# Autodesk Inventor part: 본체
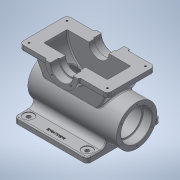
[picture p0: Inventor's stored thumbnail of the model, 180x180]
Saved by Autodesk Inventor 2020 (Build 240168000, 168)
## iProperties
Created: 2023-06
Part Number: 본체
Material: 알루미늄 6061
Document SubType Name: Modeling
Designer: mdu-01
Mass: 5748.4 g
Surface Area: 2841.69 cm^2
Volume: 2121.18 cm^3
Density: 2.71 g/cm^3
Appearance: 알루미늄 - 평지
Author: mdu-01
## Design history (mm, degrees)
sketch "스케치1"
  geometry: L1 (0, 70)-(0, -70); L2 (0, 0)-(-100, 0); L3 (0, 70)-(-45, 70); L4 (-45, 70)-(-45, 45); L5 (-45, 45)-(-100, 45); L6 (0, -70)-(-45, -70); L7 (-45, -70)-(-45, -45); L8 (-45, -45)-(-100, -45); L9 (-100, 45)-(-100, -45); 1 further point
  constraints: 18 end point, 3 perpendicular, 3 symmetric about line, 2 midpoint, 2 parallel, 1 coincident, 1 vertical
  dimensions: "d0" = 140 distance of L1.start L1.end; "d1" = 100 distance of L2.start L2.end; "d3" = 90 diameter of L4 L1; "d4" = 90 distance between parallel lines of L8 L5
revolve "회전1" sketch "스케치1" stored, may be unused: angle "d5" = 180 deg
sketch "스케치2"
  geometry: L1 (-155, -20)-(65, -20); L2 (75, -10)-(75, 100); L3 (65, 110)-(-155, 110); L4 (-165, 100)-(-165, -10); L5 (-165, -20)-(75, 110); L6 (75, -20)-(-165, 110); A1 r 10 centre (-155, 100) between (-155, 110) and (-165, 100); A2 r 10 centre (65, 100) between (75, 100) and (65, 110); A3 r 10 centre (65, -10) between (65, -20) and (75, -10); A4 r 10 centre (-155, -10) between (-165, -10) and (-155, -20); 1 further point
  constraints: 12 end point, 8 point on circle, 8 point on line, 8 tangent, 4 centre point, 3 equal radius, 2 midpoint, 2 parallel, 1 horizontal, 1 perpendicular
  dimensions: "d6" = 240 distance of L6.end L5.end; "d7" = 130 distance of L5.end L6.start; "d8" = 10 radius of A1
extrude "돌출1" join sketch "스케치2" distance "d9" = 15; taper "d10" = 0 deg
sketch "스케치3"
  geometry: C1 r 55 at (-100, 0); 1 further point
  constraints: 1 centre point
  dimensions: "d11" = 110 diameter of C1; "d12" = 100 distance of C1.centre point (0, 0)
extrude "돌출2" join sketch "스케치3" distance "d13" = 135; taper "d15" = 0 deg; dims "d14" = 107, "d16" = 0
sketch "스케치4"
  geometry: L1 (-100, -160)-(100, -160); L2 (100, -160)-(100, -145); L3 (100, -145)-(-100, -145); L4 (-100, -145)-(-100, -160); 1 further point
  constraints: 8 end point, 2 parallel, 1 horizontal, 1 perpendicular
  dimensions: "d17" = 200 distance of L3.end L2.end; "d18" = 15 distance of L2.end L1.end; "d19" = 100 distance from line of L4 point (0, 0); "d20" = 160 distance from line of L1 point (0, 0)
extrude "돌출3" join sketch "스케치4" stored distance "d21" = 200; taper "d22" = 0 deg
fillet "모깎기1" dims "d23" = 15
fillet "모깎기2" dims "d24" = 10
sketch "스케치5"
  geometry: L1 (0, 70)-(0, -70); L2 (-45, 70)-(0, 70) reference; L3 (-45, -70)-(0, -70) reference; L4 (-31, 70)-(-31, 48); L5 (-30, 47)-(-27.5, 47); L6 (-27.5, 47)-(-27.5, 32); L7 (-27.5, 32)-(-87, 32); L8 (0, 0)-(-91.923, 0); L9 (-31, -70)-(-31, -48); L10 (-30, -47)-(-27.5, -47); L11 (-27.5, -47)-(-27.5, -32); L12 (-27.5, -32)-(-87, -32); L13 (-87, 32)-(-87, -32); L14 (-31, 70)-(0, 70); L15 (-31, -70)-(0, -70); A1 r 1 centre (-30, 48) between (-31, 48) and (-30, 47); A2 r 1 centre (-30, -48) between (-30, -47) and (-31, -48)
  constraints: 26 end point, 7 symmetric about line, 4 parallel, 4 point on circle, 3 perpendicular, 2 centre point, 2 tangent, 1 collinear, 1 point on line, 1 vertical, 1 other
  dimensions: "d25" = 1 radius of A1; "d26" = 62 diameter of L4 L1; "d27" = 23 distance between parallel lines of L2 L5; "d28" = 64 distance between parallel lines of L12 L7; "d29" = 55 diameter of L6 L1; "d30" = 87 distance between parallel lines of L13 L1
revolve "회전2" sketch "스케치5" stored, may be unused: angle "d31" = 180 deg
sketch "스케치6"
  geometry: L1 (-107, -45)-(-107, -155) reference; L2 (135, -155)-(135, -45) reference; L3 (-107, -100)-(135, -100); L4 (-107, -142.5)-(-83.1, -142.5); L5 (-82, -141.4)-(-82, -138.5); L6 (-82, -138.5)-(110, -138.5); L7 (110, -138.5)-(110, -141.4); L8 (111.1, -142.5)-(135, -142.5); A1 r 1.1 centre (-83.1, -141.4) between (-83.1, -142.5) and (-82, -141.4); A2 r 1.1 centre (111.1, -141.4) between (110, -141.4) and (111.1, -142.5); 1 further point
  constraints: 12 end point, 4 point on circle, 4 tangent, 3 parallel, 2 centre point, 2 collinear, 2 midpoint, 2 perpendicular, 2 point on line, 1 equal radius
  dimensions: "d32" = 1.1 radius of A1; "d33" = 25 distance between parallel lines of L5 L1; "d34" = 77 diameter of L6 L3; "d35" = 85 diameter of L4 L3
revolve "회전3" sketch "스케치6" stored, may be unused: angle "d36" = 180 deg
fillet "모깎기3" dims "d37" = 3
fillet "모깎기4" dims "d38" = 3
sketch "스케치7"
  geometry: L1 (17, -16.754)-(177, -16.754); L2 (177, -16.754)-(177, 143.246); L3 (177, 143.246)-(17, 143.246); L4 (17, 143.246)-(17, -16.754); L5 (17, -16.754)-(177, 143.246); L6 (177, -16.754)-(17, 143.246); 1 further point
  constraints: 12 end point, 2 midpoint, 2 parallel, 1 horizontal, 1 perpendicular
  dimensions: "d39" = 160 distance of L3.end L2.end; "d40" = 160 distance of L2.end L1.end
hole "구멍1" sketch "스케치7" at (17, -16.754), (177, -16.754), (177, 143.246), (17, 143.246) diameter "d41" = 11; stored, may be unused: countersink angle "d45" = 90 deg, drill point angle "d47" = 118 deg; dims "d42" = 6, "d43" = 28, "d44" = 2, "d46" = 8
sketch "스케치8"
  geometry: L1 (-227, 3)-(-13, 3); L2 (-13, 3)-(-13, 107); L3 (-13, 107)-(-227, 107); L4 (-227, 107)-(-227, 3); L5 (-227, 3)-(-13, 107); L6 (-13, 3)-(-227, 107); 1 further point
  constraints: 12 end point, 2 midpoint, 2 parallel, 1 horizontal, 1 perpendicular
  dimensions: "d48" = 214 distance of L3.end L2.end; "d49" = 104 distance of L2.end L1.end
hole "구멍2" sketch "스케치8" at (-227, 3), (-13, 3), (-13, 107), (-227, 107) diameter "d50" = 4.917; stored, may be unused: countersink angle "d54" = 90 deg, drill point angle "d56" = 118 deg; dims "d51" = 15, "d52" = 4, "d53" = 7.5, "d55" = 15
sketch "스케치9"
  geometry: A1 r 37 centre (0, 0) between (-26.163, -26.163) and (26.163, -26.163); 1 further point
  constraints: 2 point on circle, 1 centre point, 1 coincident, 1 horizontal alignment
  dimensions: "d57" = 37 radius of A1; "d58" = 90 deg dimension on A1.centre A1.end A1.start
hole "구멍3" sketch "스케치9" at (-26.163, -26.163), (26.163, -26.163) diameter "d60" = 4.134; stored, may be unused: countersink angle "d64" = 90 deg, drill point angle "d66" = 118 deg; dims "d61" = 10, "d62" = 4, "d63" = 7.5, "d65" = 12
sketch "스케치10" dims "d68" = 97
  geometry: C1 r 38.5 at (0, 0) reference; 3 further points
  constraints: 2 vertical alignment, 1 coincident, 2 other
hole "구멍4" sketch "스케치10" at (0, 48.5) diameter "d70" = 4.134; stored, may be unused: countersink angle "d74" = 90 deg, drill point angle "d76" = 118 deg; dims "d71" = 10, "d72" = 4, "d73" = 7.5, "d75" = 12
node "작업 평면1"
sketch "스케치11"
  geometry: L1 (7, -36.754)-(187, -36.754) reference; 2 further points
  constraints: 1 vertical alignment, 1 other
  dimensions: "d80" = 15 distance from line of point (97, -21.754) L1
feature "엠보싱1" sketch "스케치11" dims "d6" = 240, "d7" = 130, "d8" = 10, "d81" = 0.5, "d82" = 0
chamfer "모따기1" distance "d83" = 1; stored, may be unused: second distance "d84" = 2, angle "d85" = 45 deg
node "솔리드1"
mirror "대칭1"
pattern_circular "원형 패턴1" dims angle "d78" = 360 deg
mirror "대칭2"
